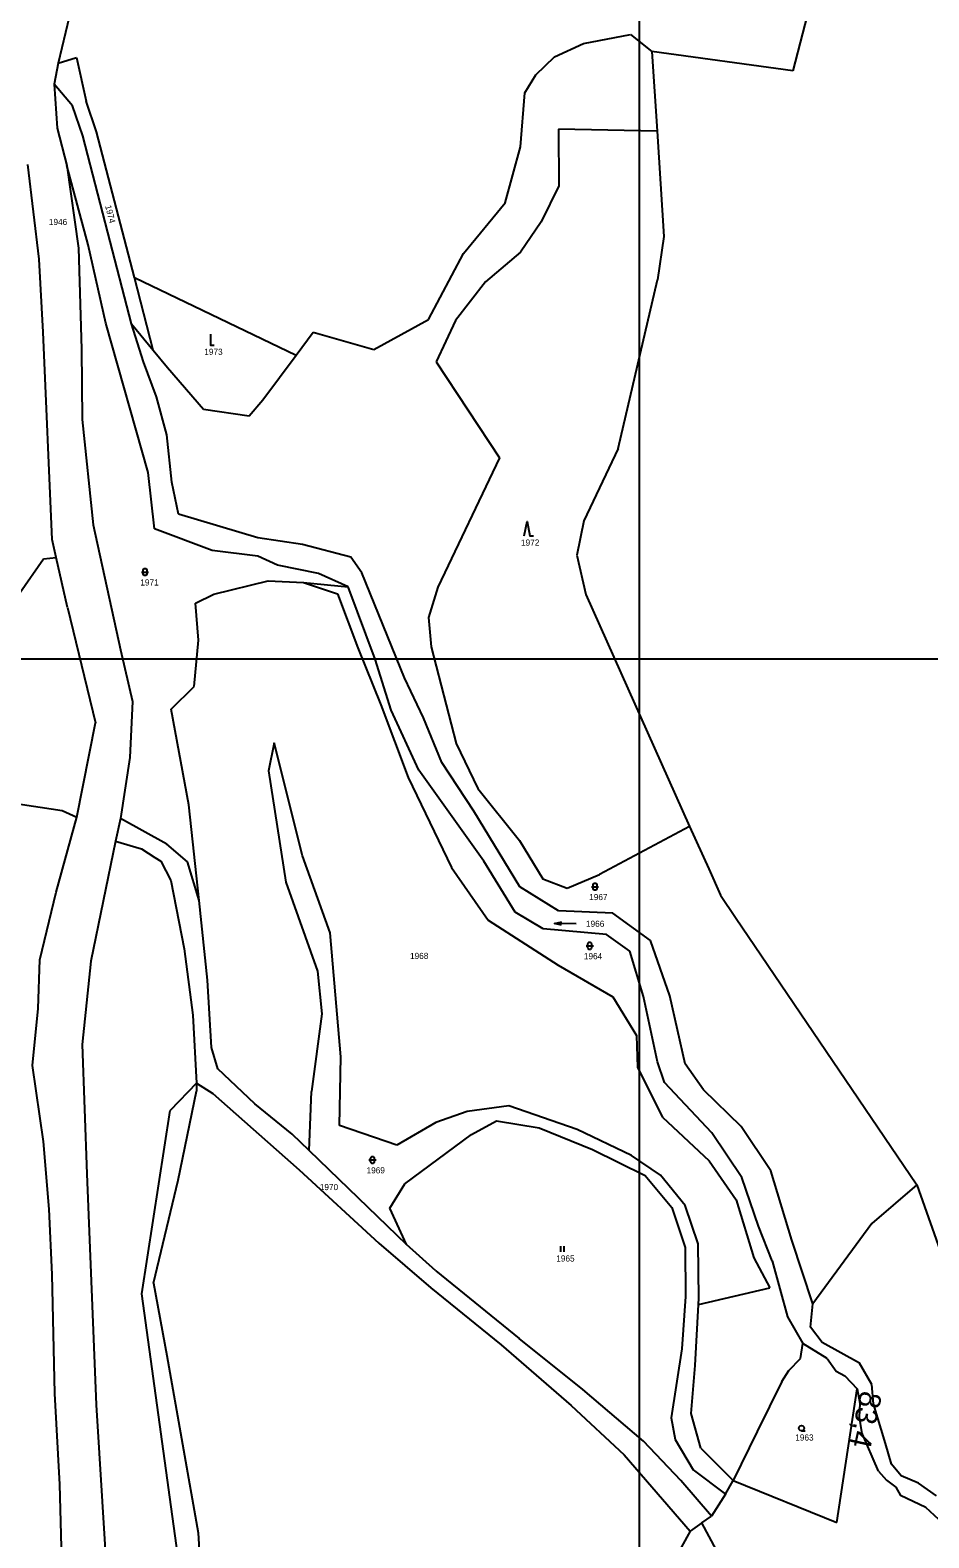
# Model space of a CAD drawing. Extents: x -801853 to -800578, y -1017479 to -1016338.
# Drawn here: x -801418.1 to -801170.2, y -1016987.3 to -1016571.7 of the extents above; entities that cross this region are included whole.
import ezdxf

# ---------------------------------------------------------------- set-up
doc = ezdxf.new("R2010")
doc.units = 0
for name, color, linetype in [('Default', 7, 'Continuous'), ('KLADY_ZMVM', 7, 'Continuous'), ('KN_HRANICE', 7, 'Continuous'), ('KN_KULTURY', 7, 'Continuous'), ('KN_PARCELY', 7, 'Continuous'), ('LEGENDA', 7, 'Continuous'), ('Vrstva 7', 7, 'Continuous'), ('Železniční svršek', 7, 'Continuous')]:
    doc.layers.add(name, color=color, linetype=linetype)

# ---------------------------------------------------------------- blocks, each defined once
blk = doc.blocks.new('302')
at = {"layer": 'Default'}
blk.add_lwpolyline([(0, 3), (0, 0), (1, 0)], dxfattribs=at)
blk = doc.blocks.new('304')
at = {"layer": 'Default'}
blk.add_lwpolyline([(0, 0), (-0.38, 0.1), (-0.65, 0.37), (-0.75, 0.74), (-0.65, 1.11), (-0.38, 1.38), (-0.01, 1.48), (0.36, 1.38), (0.63, 1.11), (0.73, 0.73), (0.63, 0.35), (0.36, 0.08), (-0.02, -0.02), (0.98, -0.02)], dxfattribs=at)
blk = doc.blocks.new('306')
at = {"layer": 'Default'}
for p, q in [((-0.5, 1.5), (-0.5, 0)), ((0.5, 0), (0.5, 1.5))]:
    blk.add_line(p, q, dxfattribs=at)
blk = doc.blocks.new('308')
at = {"layer": 'Default'}
blk.add_lwpolyline([(-0.75, 0), (0, 4), (0.75, 0), (1.75, 0)], dxfattribs=at)
blk = doc.blocks.new('316')
at = {"layer": 'Default'}
for points in [[(-1, 1), (0.27, 1), (1, 1)], [(-0.5, 1.5), (-0.4, 1.79), (-0.15, 1.97), (0.16, 1.97), (0.41, 1.79), (0.51, 1.5), (0.51, 0.5), (0.41, 0.21), (0.16, 0.03), (-0.15, 0.03), (-0.4, 0.21), (-0.5, 0.5), (-0.5, 1.5)]]:
    blk.add_lwpolyline(points, dxfattribs=at)
blk = doc.blocks.new('802')
at = {"layer": 'Default'}
blk.add_line((-3, 0), (3, 0), dxfattribs=at)
blk.add_lwpolyline([(1, 0.5), (3, 0), (1, -0.5)], dxfattribs=at)

msp = doc.modelspace()

# ---------------------------------------------------------------- linework, layer by layer
at = {"layer": 'KLADY_ZMVM'}
msp.add_line((-801250, -1017000), (-801250, -1016500), dxfattribs=at)
at = {"layer": 'KN_HRANICE'}
for p, q in [((-801196.12, -1016537.94), (-801207.69, -1016582.91)), ((-801407.27, -1016568.09), (-801410.39, -1016580.85)), ((-801265.48, -1016575.38), (-801252.47, -1016572.88)), ((-801252.47, -1016572.88), (-801246.59, -1016577.62)), ((-801273.5, -1016579.11), (-801265.48, -1016575.38)), ((-801246.59, -1016577.62), (-801245.16, -1016599.53)), ((-801207.69, -1016582.91), (-801246.59, -1016577.62)), ((-801410.39, -1016580.85), (-801411.45, -1016586.58)), ((-801410.39, -1016580.85), (-801405.28, -1016579.28)), ((-801405.28, -1016579.28), (-801402.61, -1016591.33)), ((-801278.62, -1016584.04), (-801273.5, -1016579.11)), ((-801281.61, -1016589.02), (-801278.62, -1016584.04)), ((-801411.45, -1016586.58), (-801410.59, -1016598.71)), ((-801406.4, -1016592.62), (-801411.45, -1016586.58)), ((-801282.88, -1016603.88), (-801281.61, -1016589.02)), ((-801403.57, -1016600.89), (-801406.4, -1016592.62)), ((-801399.74, -1016599.74), (-801402.61, -1016591.33)), ((-801410.59, -1016598.71), (-801407.95, -1016609.05)), ((-801396.67, -1016627.51), (-801403.57, -1016600.89)), ((-801389.32, -1016639.93), (-801399.74, -1016599.74)), ((-801245.16, -1016599.53), (-801272.31, -1016599.02)), ((-801272.31, -1016599.02), (-801272.29, -1016614.6)), ((-801245.16, -1016599.53), (-801243.27, -1016628.57)), ((-801287.04, -1016619.33), (-801282.88, -1016603.88)), ((-801415.62, -1016634.88), (-801418.74, -1016608.77)), ((-801407.95, -1016609.05), (-801404.75, -1016631.78)), ((-801402.07, -1016630.88), (-801407.95, -1016609.05)), ((-801272.29, -1016614.6), (-801277.12, -1016624.55)), ((-801298.6, -1016633.32), (-801287.04, -1016619.33)), ((-801390.11, -1016652.67), (-801396.67, -1016627.51)), ((-801277.12, -1016624.55), (-801282.8, -1016632.88)), ((-801404.75, -1016631.78), (-801403.95, -1016659.67)), ((-801397.17, -1016652.47), (-801402.07, -1016630.88)), ((-801243.27, -1016628.57), (-801245.06, -1016640.51)), ((-801414.44, -1016654.93), (-801415.62, -1016634.88)), ((-801308.25, -1016651.49), (-801298.6, -1016633.32)), ((-801282.8, -1016632.88), (-801292.46, -1016641.08)), ((-801384.13, -1016659.93), (-801389.32, -1016639.93)), ((-801389.32, -1016639.93), (-801344.74, -1016661.3)), ((-801292.46, -1016641.08), (-801300.77, -1016651.72)), ((-801255.91, -1016687.07), (-801245.06, -1016640.51)), ((-801385.5, -1016693.61), (-801397.17, -1016652.47)), ((-801386.82, -1016663.1), (-801390.11, -1016652.67)), ((-801390.11, -1016652.67), (-801384.13, -1016659.93)), ((-801323.26, -1016659.76), (-801308.25, -1016651.49)), ((-801300.77, -1016651.72), (-801306.09, -1016663.1)), ((-801411.98, -1016712.14), (-801414.44, -1016654.93)), ((-801344.74, -1016661.3), (-801340.05, -1016654.98)), ((-801340.05, -1016654.98), (-801323.26, -1016659.76)), ((-801403.95, -1016659.67), (-801403.72, -1016679)), ((-801384.13, -1016659.93), (-801380.18, -1016664.72)), ((-801383.23, -1016672.78), (-801386.82, -1016663.1)), ((-801380.18, -1016664.72), (-801370.23, -1016676.2)), ((-801353.89, -1016673.62), (-801344.74, -1016661.3)), ((-801306.09, -1016663.1), (-801288.67, -1016689.61)), ((-801380.38, -1016683.29), (-801383.23, -1016672.78)), ((-801357.66, -1016678), (-801353.89, -1016673.62)), ((-801370.23, -1016676.2), (-801357.66, -1016678)), ((-801403.72, -1016679), (-801400.68, -1016708.1)), ((-801379, -1016696.34), (-801380.38, -1016683.29)), ((-801288.67, -1016689.61), (-801305.61, -1016725.29)), ((-801255.91, -1016687.07), (-801265.38, -1016707.01)), ((-801383.79, -1016709.22), (-801385.5, -1016693.61)), ((-801377.17, -1016705.1), (-801379, -1016696.34)), ((-801355.25, -1016711.7), (-801377.17, -1016705.1)), ((-801400.68, -1016708.1), (-801393.15, -1016742.52)), ((-801367.9, -1016715.14), (-801383.79, -1016709.22)), ((-801265.38, -1016707.01), (-801267.26, -1016716.41)), ((-801410.87, -1016717.08), (-801411.98, -1016712.14)), ((-801355.3, -1016716.73), (-801367.9, -1016715.14)), ((-801342.96, -1016713.48), (-801355.25, -1016711.7)), ((-801329.61, -1016716.98), (-801342.96, -1016713.48)), ((-801435.35, -1016747.43), (-801414.37, -1016717.41)), ((-801414.37, -1016717.41), (-801410.87, -1016717.08)), ((-801407.76, -1016730.91), (-801410.87, -1016717.08)), ((-801349.81, -1016719.18), (-801355.3, -1016716.73)), ((-801338.55, -1016721.48), (-801349.81, -1016719.18)), ((-801326.57, -1016721.34), (-801329.61, -1016716.98)), ((-801267.26, -1016716.41), (-801264.86, -1016727.26)), ((-801367.4, -1016727.15), (-801352.44, -1016723.55)), ((-801352.44, -1016723.55), (-801342.72, -1016723.96)), ((-801330.35, -1016725.21), (-801338.55, -1016721.48)), ((-801314.87, -1016750.25), (-801326.57, -1016721.34)), ((-801372.5, -1016729.63), (-801367.4, -1016727.15)), ((-801342.72, -1016723.96), (-801333.29, -1016727.12)), ((-801342.72, -1016723.96), (-801330.35, -1016725.21)), ((-801333.29, -1016727.12), (-801327.68, -1016742.01)), ((-801322.92, -1016745.08), (-801330.35, -1016725.21)), ((-801305.61, -1016725.29), (-801308.25, -1016733.62)), ((-801264.86, -1016727.26), (-801236.19, -1016791.22)), ((-801407.76, -1016730.91), (-801400.05, -1016762.62)), ((-801371.61, -1016739.91), (-801372.5, -1016729.63)), ((-801308.25, -1016733.62), (-801307.47, -1016741.69)), ((-801372.85, -1016752.66), (-801371.61, -1016739.91)), ((-801393.15, -1016742.52), (-801389.82, -1016756.82)), ((-801327.68, -1016742.01), (-801321.38, -1016757.65)), ((-801307.47, -1016741.69), (-801300.62, -1016768.35)), ((-801318.5, -1016759.18), (-801322.92, -1016745.08)), ((-801379.21, -1016758.88), (-801372.85, -1016752.66)), ((-801309.57, -1016761.31), (-801314.87, -1016750.25)), ((-801389.82, -1016756.82), (-801390.61, -1016772.19)), ((-801374.32, -1016785.25), (-801379.21, -1016758.88)), ((-801321.38, -1016757.65), (-801313.82, -1016777.7)), ((-801310.89, -1016775.73), (-801318.5, -1016759.18)), ((-801405.24, -1016788.68), (-801400.05, -1016762.62)), ((-801304.52, -1016773.59), (-801309.57, -1016761.31)), ((-801350.77, -1016768.15), (-801352.35, -1016775.89)), ((-801342.98, -1016799.28), (-801350.77, -1016768.15)), ((-801300.62, -1016768.35), (-801294.6, -1016780.8)), ((-801390.61, -1016772.19), (-801393.13, -1016789.06)), ((-801352.35, -1016775.89), (-801347.54, -1016806.61)), ((-801292.99, -1016800.81), (-801310.89, -1016775.73)), ((-801295.75, -1016787.05), (-801304.52, -1016773.59)), ((-801313.82, -1016777.7), (-801301.84, -1016802.52)), ((-801294.6, -1016780.8), (-801283.09, -1016795.11)), ((-801423.24, -1016784.75), (-801409.24, -1016786.85)), ((-801371.48, -1016811.65), (-801374.32, -1016785.25)), ((-801410.88, -1016809.36), (-801405.24, -1016788.68)), ((-801409.24, -1016786.85), (-801405.24, -1016788.68)), ((-801393.13, -1016789.06), (-801394.56, -1016795.27)), ((-801380.37, -1016796.09), (-801393.13, -1016789.06)), ((-801282.99, -1016807.91), (-801295.75, -1016787.05)), ((-801236.19, -1016791.22), (-801261.04, -1016804.5)), ((-801236.19, -1016791.22), (-801230.93, -1016802.94)), ((-801394.56, -1016795.27), (-801401.33, -1016828.35)), ((-801394.56, -1016795.27), (-801387.4, -1016797.43)), ((-801387.4, -1016797.43), (-801383.64, -1016799.76)), ((-801374.7, -1016801.01), (-801380.37, -1016796.09)), ((-801283.09, -1016795.11), (-801276.64, -1016805.63)), ((-801383.64, -1016799.76), (-801382.03, -1016800.75)), ((-801382.03, -1016800.75), (-801379.27, -1016806.1)), ((-801371.48, -1016811.65), (-801374.7, -1016801.01)), ((-801335.34, -1016820.59), (-801342.98, -1016799.28)), ((-801301.84, -1016802.52), (-801291.71, -1016817.07)), ((-801284.31, -1016814.88), (-801292.99, -1016800.81)), ((-801379.27, -1016806.1), (-801375.63, -1016825)), ((-801347.54, -1016806.61), (-801338.83, -1016831.13)), ((-801276.64, -1016805.63), (-801270, -1016808.23)), ((-801270, -1016808.23), (-801261.04, -1016804.5)), ((-801230.93, -1016802.94), (-801227.69, -1016810.17)), ((-801415.36, -1016828.03), (-801410.88, -1016809.36)), ((-801272.38, -1016814.51), (-801282.99, -1016807.91)), ((-801227.69, -1016810.17), (-801223.54, -1016816.29)), ((-801369.16, -1016833.55), (-801371.48, -1016811.65)), ((-801276.59, -1016819.48), (-801284.31, -1016814.88)), ((-801257.35, -1016815.11), (-801272.38, -1016814.51)), ((-801291.71, -1016817.07), (-801272.46, -1016829.44)), ((-801246.96, -1016822.66), (-801257.35, -1016815.11)), ((-801223.54, -1016816.29), (-801173.56, -1016890)), ((-801332.36, -1016854.72), (-801335.34, -1016820.59)), ((-801259.11, -1016821.03), (-801276.59, -1016819.48)), ((-801252.7, -1016825.56), (-801259.11, -1016821.03)), ((-801241.66, -1016837.9), (-801246.96, -1016822.66)), ((-801375.63, -1016825), (-801373.16, -1016843.25)), ((-801248.92, -1016838.05), (-801252.7, -1016825.56)), ((-801415.85, -1016841.4), (-801415.36, -1016828.03)), ((-801401.33, -1016828.35), (-801403.76, -1016851.31)), ((-801338.83, -1016831.13), (-801337.62, -1016842.89)), ((-801272.46, -1016829.44), (-801257.35, -1016838.15)), ((-801368.08, -1016852.12), (-801369.16, -1016833.55)), ((-801257.35, -1016838.15), (-801250.82, -1016848.86)), ((-801245.06, -1016856.14), (-801248.92, -1016838.05)), ((-801237.39, -1016856.65), (-801241.66, -1016837.9)), ((-801417.41, -1016857.13), (-801415.85, -1016841.4)), ((-801373.16, -1016843.25), (-801372.19, -1016862.02)), ((-801337.62, -1016842.89), (-801340.5, -1016864.27)), ((-801403.76, -1016851.31), (-801402.47, -1016886.95)), ((-801366.35, -1016858.03), (-801368.08, -1016852.12)), ((-801250.82, -1016848.86), (-801250.6, -1016857.65)), ((-801332.71, -1016873.66), (-801332.36, -1016854.72)), ((-801243.11, -1016861.82), (-801245.06, -1016856.14)), ((-801414.36, -1016878.03), (-801417.41, -1016857.13)), ((-801356.14, -1016867.7), (-801366.35, -1016858.03)), ((-801250.6, -1016857.65), (-801243.71, -1016871.35)), ((-801232.37, -1016863.85), (-801237.39, -1016856.65)), ((-801372.19, -1016862.02), (-801379.41, -1016869.49)), ((-801377.22, -1016888.71), (-801372.22, -1016864.23)), ((-801372.19, -1016862.02), (-801372.22, -1016864.23)), ((-801372.19, -1016862.02), (-801367.69, -1016864.79)), ((-801367.69, -1016864.79), (-801343.92, -1016885.84)), ((-801341.13, -1016880.54), (-801340.5, -1016864.27)), ((-801230.06, -1016875.69), (-801243.11, -1016861.82)), ((-801222, -1016873.95), (-801232.37, -1016863.85)), ((-801345.81, -1016876.03), (-801356.14, -1016867.7)), ((-801286.09, -1016868.26), (-801297.52, -1016869.84)), ((-801267.25, -1016874.77), (-801286.09, -1016868.26)), ((-801387.26, -1016920.03), (-801379.41, -1016869.49)), ((-801306.18, -1016872.83), (-801316.9, -1016879.08)), ((-801297.52, -1016869.84), (-801306.18, -1016872.83)), ((-801296.32, -1016876.18), (-801289.49, -1016872.35)), ((-801289.49, -1016872.35), (-801277.67, -1016874.3)), ((-801243.71, -1016871.35), (-801230.84, -1016883.39)), ((-801341.13, -1016880.54), (-801345.81, -1016876.03)), ((-801316.9, -1016879.08), (-801332.71, -1016873.66)), ((-801314.72, -1016889.78), (-801296.32, -1016876.18)), ((-801277.67, -1016874.3), (-801262.95, -1016880.25)), ((-801252.23, -1016881.89), (-801267.25, -1016874.77)), ((-801221.82, -1016887.99), (-801230.06, -1016875.69)), ((-801213.83, -1016886.15), (-801222, -1016873.95)), ((-801412.79, -1016896.74), (-801414.36, -1016878.03)), ((-801332.81, -1016888.54), (-801341.13, -1016880.54)), ((-801262.95, -1016880.25), (-801248.49, -1016887.43)), ((-801244.2, -1016887.31), (-801252.23, -1016881.89)), ((-801230.84, -1016883.39), (-801223.31, -1016894.13)), ((-801402.47, -1016886.95), (-801399.88, -1016950.65)), ((-801384.02, -1016917.11), (-801377.22, -1016888.71)), ((-801343.92, -1016885.84), (-801321.91, -1016906.13)), ((-801314.29, -1016906.43), (-801332.81, -1016888.54)), ((-801318.83, -1016896.43), (-801314.72, -1016889.78)), ((-801248.49, -1016887.43), (-801241.1, -1016896.25)), ((-801237.42, -1016895.71), (-801244.2, -1016887.31)), ((-801217.2, -1016901.37), (-801221.82, -1016887.99)), ((-801208, -1016905.29), (-801213.83, -1016886.15)), ((-801173.56, -1016890), (-801185.97, -1016900.67)), ((-801173.56, -1016890), (-801157.02, -1016936.79)), ((-801412.02, -1016914.76), (-801412.79, -1016896.74)), ((-801314.29, -1016906.43), (-801318.83, -1016896.43)), ((-801241.1, -1016896.25), (-801237.39, -1016907.27)), ((-801233.81, -1016906.24), (-801237.42, -1016895.71)), ((-801223.31, -1016894.13), (-801218.46, -1016910.15)), ((-801213.44, -1016910.95), (-801217.2, -1016901.37)), ((-801185.97, -1016900.67), (-801202.21, -1016922.85)), ((-801321.91, -1016906.13), (-801307.61, -1016918.38)), ((-801306.18, -1016913.74), (-801314.29, -1016906.43)), ((-801233.68, -1016921.23), (-801233.81, -1016906.24)), ((-801202.21, -1016922.85), (-801208, -1016905.29)), ((-801237.39, -1016907.27), (-801237.33, -1016920.82)), ((-801218.46, -1016910.15), (-801214.06, -1016918.38)), ((-801411.25, -1016947.54), (-801412.02, -1016914.76)), ((-801306.18, -1016913.74), (-801283.23, -1016932.34)), ((-801213.44, -1016910.95), (-801209.21, -1016926.4)), ((-801384.02, -1016917.11), (-801380.41, -1016937.07)), ((-801307.61, -1016918.38), (-801288.2, -1016934.1)), ((-801233.77, -1016922.99), (-801214.06, -1016918.38)), ((-801376.54, -1016997.57), (-801387.26, -1016920.03)), ((-801237.33, -1016920.82), (-801238.33, -1016935.25)), ((-801234.66, -1016939.84), (-801233.77, -1016922.99)), ((-801233.77, -1016922.99), (-801233.68, -1016921.23)), ((-801202.84, -1016929.27), (-801202.21, -1016922.85)), ((-801209.21, -1016926.4), (-801204.99, -1016933.78)), ((-801199.62, -1016933.47), (-801202.84, -1016929.27)), ((-801288.2, -1016934.1), (-801268.85, -1016950.86)), ((-801265.6, -1016946.42), (-801283.23, -1016932.34)), ((-801238.33, -1016935.25), (-801241.27, -1016954.27)), ((-801205.59, -1016937.87), (-801204.99, -1016933.78)), ((-801198.22, -1016937.87), (-801204.99, -1016933.78)), ((-801189.32, -1016939.19), (-801199.62, -1016933.47)), ((-801380.41, -1016937.07), (-801371.73, -1016985.95)), ((-801208.82, -1016941.19), (-801205.59, -1016937.87)), ((-801198.22, -1016937.87), (-801195.74, -1016941.4)), ((-801185.94, -1016945.08), (-801189.32, -1016939.19)), ((-801235.8, -1016953), (-801234.66, -1016939.84)), ((-801210.76, -1016944.18), (-801208.82, -1016941.19)), ((-801195.74, -1016941.4), (-801193.35, -1016942.64)), ((-801193.35, -1016942.64), (-801190, -1016946.24)), ((-801409.87, -1016972.62), (-801411.25, -1016947.54)), ((-801248.92, -1016960.67), (-801265.6, -1016946.42)), ((-801210.76, -1016944.18), (-801217.52, -1016958.04)), ((-801195.61, -1016983.11), (-801190, -1016946.24)), ((-801190, -1016946.24), (-801189.23, -1016950.15)), ((-801185.46, -1016950.36), (-801185.94, -1016945.08)), ((-801399.88, -1016950.65), (-801397.37, -1016990.64)), ((-801268.85, -1016950.86), (-801254.2, -1016964.46)), ((-801189.23, -1016950.15), (-801189.39, -1016954.09)), ((-801182.14, -1016961.34), (-801185.46, -1016950.36)), ((-801241.27, -1016954.27), (-801240.16, -1016960.25)), ((-801233.13, -1016962.64), (-801235.8, -1016953)), ((-801189.39, -1016954.09), (-801188.76, -1016958.13)), ((-801240.16, -1016960.25), (-801235.24, -1016968.56)), ((-801217.52, -1016958.04), (-801224.21, -1016971.53)), ((-801184.14, -1016968.93), (-801188.76, -1016958.13)), ((-801254.2, -1016964.46), (-801236.03, -1016985.46)), ((-801238.61, -1016971.5), (-801248.92, -1016960.67)), ((-801233.13, -1016962.64), (-801224.21, -1016971.53)), ((-801180.53, -1016967.01), (-801182.14, -1016961.34)), ((-801235.24, -1016968.56), (-801226.27, -1016975.26)), ((-801177.89, -1016970.27), (-801180.53, -1016967.01)), ((-801409.16, -1017001.88), (-801409.87, -1016972.62)), ((-801230.13, -1016981.38), (-801238.61, -1016971.5)), ((-801226.27, -1016975.26), (-801224.21, -1016971.53)), ((-801224.21, -1016971.53), (-801195.61, -1016983.11)), ((-801184.14, -1016968.93), (-801181.87, -1016971.45)), ((-801181.87, -1016971.45), (-801179.3, -1016973.37)), ((-801173.07, -1016972.28), (-801177.89, -1016970.27)), ((-801168.07, -1016975.74), (-801173.07, -1016972.28)), ((-801226.27, -1016975.26), (-801230.13, -1016981.38)), ((-801179.3, -1016973.37), (-801178.02, -1016975.61)), ((-801171.01, -1016978.97), (-801178.02, -1016975.61)), ((-801165.08, -1016984.43), (-801171.01, -1016978.97)), ((-801232.81, -1016983.18), (-801236.03, -1016985.46)), ((-801232.81, -1016983.18), (-801230.13, -1016981.38)), ((-801228.75, -1016990.75), (-801232.81, -1016983.18)), ((-801371.73, -1016985.95), (-801370.4, -1017006.86)), ((-801236.03, -1016985.46), (-801248.21, -1017007.29))]:
    msp.add_line(p, q, dxfattribs=at)
at = {"layer": 'LEGENDA'}
msp.add_lwpolyline([(-801559.16, -1017339.08), (-800718.16, -1017339.08), (-800718.16, -1016745.08), (-801559.16, -1016745.08)], close=True, dxfattribs=at)
at = {"layer": 'Železniční svršek'}
msp.add_arc((-801431.93, -1016905.94), 345.8, 311.7457, 358.6036, dxfattribs=at)

# ---------------------------------------------------------------- block references
at = {"layer": 'KN_KULTURY'}
for name, p in [('302', (-801368.36, -1016658.52)), ('308', (-801281.03, -1016711.12)), ('316', (-801386.39, -1016722.1)), ('316', (-801262.29, -1016808.83)), ('316', (-801263.73, -1016825.13)), ('316', (-801323.66, -1016884.16)), ('306', (-801271.29, -1016908.45)), ('304', (-801205.35, -1016957.81))]:
    msp.add_blockref(name, p, dxfattribs=at)
at = {"layer": 'KN_KULTURY', "rotation": 179.221198}
msp.add_blockref('802', (-801270.48, -1016817.99), dxfattribs=at)

# ---------------------------------------------------------------- texts
at = {"layer": 'KN_PARCELY'}
for s, p in [('1946', (-801412.91, -1016625.44)), ('1973', (-801370.04, -1016661.22)), ('1972', (-801282.69, -1016713.82)), ('1971', (-801387.68, -1016724.8)), ('1967', (-801263.89, -1016811.53)), ('1966', (-801264.78, -1016818.89)), ('1968', (-801313.3, -1016827.76)), ('1964', (-801265.36, -1016827.83)), ('1969', (-801325.29, -1016886.86)), ('1970', (-801338.19, -1016891.47)), ('1965', (-801272.97, -1016911.15)), ('1963', (-801207.06, -1016960.51))]:
    msp.add_text(s, height=1.7, dxfattribs=at).set_placement(p)
msp.add_text('1974', height=1.7, rotation=284.474, dxfattribs=at).set_placement((-801397.42, -1016620.19))
at = {"layer": 'Vrstva 7'}
msp.add_text('83,4', height=6, rotation=257.8494, dxfattribs=at).set_placement((-801188.95, -1016946.51))

doc.saveas('drawing.dxf')
